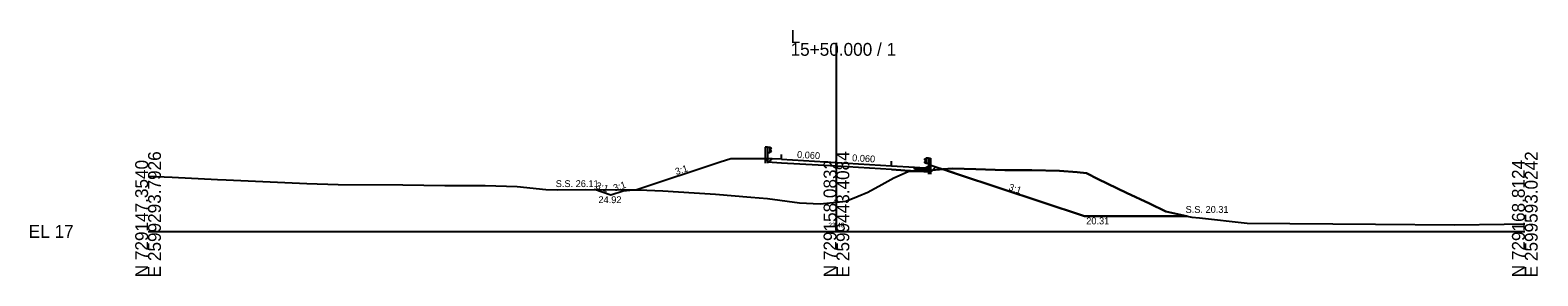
# Model space of a CAD drawing. Extents: x -26 to 3303, y -10 to 9555.
# Drawn here: x 974.3 to 1302.8, y 990.3 to 1043.9 of the extents above; entities that cross this region are included whole.
import ezdxf

# ---------------------------------------------------------------- set-up
doc = ezdxf.new("R2010")
doc.units = 0
for name, color, linetype in [('Exist Cross Section Cell', 7, 'Continuous'), ('Exist XS Center Line Elevation Label', 7, 'Continuous'), ('Exist XS Ground Line', 7, 'Continuous'), ('Prop XS Ditch Slope Text', 7, 'Continuous'), ('Prop XS Ditch Standard Text', 7, 'Continuous'), ('Prop XS Dump Level', 7, 'Continuous'), ('Prop XS Earthwork Shape', 7, 'Continuous'), ('Prop XS EOT Tick Mark', 7, 'Continuous'), ('Prop XS Finish Grade', 7, 'Continuous'), ('Prop XS Finish Grade Earthwork', 7, 'Continuous'), ('Prop XS Finish Grade Paved Shoulder', 7, 'Continuous'), ('Prop XS Finish Grade Pavement', 7, 'Continuous'), ('Prop XS Pvmt Edge Slope', 7, 'Continuous'), ('Prop XS SE Text', 7, 'Continuous'), ('Prop XS Side Slope Text', 7, 'Continuous'), ('Prop XS SS Elevation Text', 7, 'Continuous'), ('Prop XS Subgrade Earthwork', 7, 'Continuous'), ('Typical Curb CELL', 7, 'Continuous'), ('Typical Guardrail CELL', 7, 'Continuous')]:
    doc.layers.add(name, color=color, linetype=linetype)

msp = doc.modelspace()

# ---------------------------------------------------------------- linework, layer by layer
at = {"layer": 'Exist Cross Section Cell'}
for p, q in [((1150, 1000), (1150, 1041.13)), ((1000, 1000), (1150, 1000)), ((1150, 1000), (1300, 1000))]:
    msp.add_line(p, q, dxfattribs=at)
at = {"layer": 'Exist XS Ground Line'}
msp.add_lwpolyline([(1000, 1012.08), (1005.25, 1011.85), (1015.13, 1011.32), (1017, 1011.25), (1018.63, 1011.19), (1034.61, 1010.47), (1041.39, 1010.28), (1055.54, 1010.16), (1064.7, 1010.01), (1068.48, 1010.01), (1073.45, 1010), (1080.45, 1009.8), (1086.71, 1009.19), (1089.15, 1009.08), (1095.38, 1009.13), (1104.89, 1009.09), (1108.68, 1009.02), (1112.17, 1008.87), (1118.98, 1008.42), (1123.67, 1008.15), (1131.38, 1007.46), (1134.99, 1007.19), (1141.95, 1006.24), (1146.45, 1006), (1150, 1006.4), (1152.08, 1006.64), (1154.75, 1007.7), (1156.83, 1008.6), (1159.91, 1010.26), (1162.5, 1011.68), (1165.66, 1013.06), (1169.68, 1013.3), (1175.28, 1013.71), (1180.39, 1013.57), (1186.71, 1013.37), (1192.61, 1013.36), (1198.62, 1013.23), (1202.42, 1012.94), (1204.51, 1012.74), (1207.06, 1011.42), (1213.21, 1008.46), (1218.19, 1006.11), (1221.75, 1004.32), (1226.33, 1003.33), (1227.47, 1003.12), (1229.11, 1002.94), (1239.52, 1001.78), (1267.47, 1001.58), (1284.68, 1001.41), (1295.49, 1001.59), (1300, 1001.65)], dxfattribs=at)
at = {"layer": 'Prop XS Dump Level'}
for p, q in [((1138, 1015.76), (1150, 1015.04)), ((1150, 1015.04), (1162, 1014.32))]:
    msp.add_line(p, q, dxfattribs=at)
at = {"layer": 'Prop XS Earthwork Shape'}
for points in [[(1135.21, 1015.1), (1134.43, 1015.88), (1127, 1015.88), (1124.64, 1015.1), (1106.52, 1009.06), (1108.68, 1009.02), (1112.17, 1008.87), (1118.98, 1008.42), (1123.67, 1008.15), (1131.38, 1007.46), (1134.99, 1007.19), (1141.95, 1006.24), (1146.45, 1006), (1150, 1006.4), (1152.08, 1006.64), (1154.75, 1007.7), (1156.83, 1008.6), (1159.91, 1010.26), (1162.5, 1011.68), (1165.66, 1013.06), (1167.44, 1013.16), (1164.89, 1013.32), (1164, 1013.37), (1162, 1013.49), (1150, 1014.21), (1138, 1014.93), (1136, 1015.05)], [(1138, 1014.93), (1136, 1015.05), (1135.21, 1015.1), (1134.43, 1015.88), (1127, 1015.88), (1124.64, 1015.1), (1106.52, 1009.06), (1108.68, 1009.02), (1112.17, 1008.87), (1118.98, 1008.42), (1123.67, 1008.15), (1131.38, 1007.46), (1134.99, 1007.19), (1141.95, 1006.24), (1146.45, 1006), (1150, 1006.4), (1152.08, 1006.64), (1154.75, 1007.7), (1156.83, 1008.6), (1159.91, 1010.26), (1162.5, 1011.68), (1165.66, 1013.06), (1167.44, 1013.16), (1164.89, 1013.32), (1164, 1013.37), (1162, 1013.49), (1150, 1014.21)], [(1170.56, 1012.98), (1170.98, 1013.4), (1169.68, 1013.3), (1167.44, 1013.16)], [(1170.56, 1012.98), (1170.98, 1013.4), (1169.68, 1013.3), (1167.44, 1013.16)], [(1170.98, 1013.4), (1171.68, 1014.09), (1173.26, 1013.56)], [(1171.68, 1014.09), (1173.26, 1013.56), (1170.98, 1013.4)], [(1173.26, 1013.56), (1176.4, 1012.52), (1204.02, 1003.31), (1226.43, 1003.31), (1226.33, 1003.33), (1221.75, 1004.32), (1218.19, 1006.11), (1213.21, 1008.46), (1207.06, 1011.42), (1204.51, 1012.74), (1202.42, 1012.94), (1198.62, 1013.23), (1192.61, 1013.36), (1186.71, 1013.37), (1180.39, 1013.57), (1175.28, 1013.71)], [(1173.26, 1013.56), (1175.28, 1013.71), (1180.39, 1013.57), (1186.71, 1013.37), (1192.61, 1013.36), (1198.62, 1013.23), (1202.42, 1012.94), (1204.51, 1012.74), (1207.06, 1011.42), (1213.21, 1008.46), (1218.19, 1006.11), (1221.75, 1004.32), (1226.33, 1003.33), (1226.43, 1003.31), (1204.02, 1003.31), (1176.4, 1012.52)], [(1106.52, 1009.06), (1103.52, 1008.81), (1100.86, 1007.92), (1097.25, 1009.12), (1104.89, 1009.09)], [(1106.52, 1009.06), (1103.52, 1008.81), (1100.86, 1007.92), (1097.25, 1009.12), (1104.89, 1009.09)]]:
    msp.add_lwpolyline(points, close=True, dxfattribs=at)
at = {"layer": 'Prop XS EOT Tick Mark'}
for p, q in [((1138, 1015.76), (1138, 1016.76)), ((1162, 1014.32), (1162, 1015.32))]:
    msp.add_line(p, q, dxfattribs=at)
at = {"layer": 'Prop XS Finish Grade'}
for p, q in [((1136, 1015.88), (1134.43, 1015.88)), ((1170.03, 1014.21), (1170.56, 1014.46)), ((1170.56, 1014.46), (1171.68, 1014.09))]:
    msp.add_line(p, q, dxfattribs=at)
at = {"layer": 'Prop XS Finish Grade Earthwork'}
for p, q in [((1127, 1015.88), (1124.64, 1015.1)), ((1134.43, 1015.88), (1127, 1015.88)), ((1124.64, 1015.1), (1106.52, 1009.06)), ((1171.68, 1014.09), (1176.4, 1012.52)), ((1176.4, 1012.52), (1204.02, 1003.31)), ((1100.86, 1007.92), (1097.25, 1009.12)), ((1103.52, 1008.81), (1100.86, 1007.92)), ((1106.52, 1009.06), (1103.52, 1008.81)), ((1226.43, 1003.31), (1204.02, 1003.31))]:
    msp.add_line(p, q, dxfattribs=at)
at = {"layer": 'Prop XS Finish Grade Paved Shoulder'}
for p, q in [((1138, 1015.76), (1136, 1015.88)), ((1162, 1014.32), (1167, 1014.02))]:
    msp.add_line(p, q, dxfattribs=at)
at = {"layer": 'Prop XS Finish Grade Pavement'}
for p, q in [((1138, 1015.76), (1150, 1015.04)), ((1150, 1015.04), (1162, 1014.32))]:
    msp.add_line(p, q, dxfattribs=at)
at = {"layer": 'Prop XS Pvmt Edge Slope'}
for p, q in [((1135.21, 1015.1), (1134.43, 1015.88)), ((1136, 1015.88), (1135.21, 1015.1)), ((1170.01, 1013.53), (1170.56, 1012.98)), ((1170.56, 1012.98), (1171.68, 1014.09))]:
    msp.add_line(p, q, dxfattribs=at)
at = {"layer": 'Prop XS Subgrade Earthwork'}
for p, q in [((1135.21, 1015.1), (1134.43, 1015.88)), ((1136, 1015.05), (1135.21, 1015.1)), ((1138, 1014.93), (1136, 1015.05)), ((1150, 1014.21), (1138, 1014.93)), ((1162, 1013.49), (1150, 1014.21)), ((1162, 1013.49), (1164, 1013.37)), ((1164, 1013.37), (1164.89, 1013.32)), ((1164.89, 1013.32), (1170.56, 1012.98)), ((1170.56, 1012.98), (1171.68, 1014.09))]:
    msp.add_line(p, q, dxfattribs=at)
at = {"layer": 'Typical Curb CELL'}
for p, q in [((1166.99, 1013.61), (1167, 1014.01)), ((1170.01, 1013.53), (1166.99, 1013.61)), ((1167, 1014.02), (1167, 1014.02)), ((1167.01, 1014.02), (1169.33, 1013.88)), ((1167.23, 1013.75), (1167.32, 1013.87)), ((1167.35, 1013.76), (1167.23, 1013.75)), ((1167.32, 1013.87), (1167.35, 1013.76)), ((1167.99, 1013.68), (1168.06, 1013.8)), ((1168.16, 1013.72), (1167.99, 1013.68)), ((1168.06, 1013.8), (1168.16, 1013.72)), ((1168.48, 1013.72), (1168.57, 1013.84)), ((1168.6, 1013.72), (1168.48, 1013.72)), ((1168.57, 1013.84), (1168.6, 1013.72)), ((1169.24, 1013.65), (1169.31, 1013.76)), ((1169.41, 1013.69), (1169.24, 1013.65)), ((1169.31, 1013.76), (1169.41, 1013.69)), ((1169.33, 1013.88), (1170.03, 1014.21)), ((1169.83, 1013.88), (1169.84, 1013.79)), ((1169.98, 1013.83), (1169.83, 1013.88)), ((1169.84, 1013.79), (1169.98, 1013.83)), ((1170.01, 1013.53), (1170.03, 1014.21))]:
    msp.add_line(p, q, dxfattribs=at)
for centre in [(1167.09, 1013.84), (1167.13, 1013.97), (1167.49, 1013.88), (1167.55, 1013.7), (1167.6, 1013.67), (1167.64, 1013.79), (1167.71, 1013.79), (1167.76, 1013.82), (1167.81, 1013.7), (1168, 1013.74), (1168.21, 1013.72), (1168.23, 1013.77), (1168.24, 1013.82), (1168.29, 1013.68), (1168.39, 1013.72), (1168.48, 1013.73), (1168.6, 1013.68), (1168.8, 1013.67), (1168.85, 1013.64), (1168.89, 1013.76), (1169.01, 1013.79), (1169.06, 1013.67), (1169.25, 1013.71), (1169.28, 1013.6), (1169.46, 1013.68), (1169.48, 1013.73), (1169.73, 1013.7), (1169.85, 1013.65), (1169.95, 1013.92)]:
    msp.add_circle(centre, 0.00802, dxfattribs=at)
msp.add_arc((1167.01, 1014.01), 0.0104, 86.5213, 178.5693, dxfattribs=at)
at = {"layer": 'Typical Guardrail CELL'}
for p, q in [((1135, 1018.37), (1134.5, 1018.37)), ((1134.5, 1018.37), (1134.5, 1015.88)), ((1135, 1015.88), (1134.5, 1015.88)), ((1134.5, 1015.88), (1134.5, 1014.87)), ((1135, 1018.37), (1135, 1015.88)), ((1135, 1018.37), (1135.5, 1018.37)), ((1135, 1017.21), (1135.5, 1017.21)), ((1135, 1015.88), (1135, 1014.87)), ((1135.5, 1018.37), (1135.5, 1017.21)), ((1135.5, 1018.37), (1135.79, 1018.17)), ((1135.5, 1017.84), (1135.79, 1018.04)), ((1135.5, 1017.79), (1135.5, 1017.84)), ((1135.5, 1017.79), (1135.5, 1017.74)), ((1135.5, 1017.74), (1135.79, 1017.54)), ((1135.5, 1017.21), (1135.79, 1017.41)), ((1169.53, 1015.99), (1169.24, 1015.79)), ((1169.53, 1015.46), (1169.24, 1015.66)), ((1169.53, 1015.36), (1169.24, 1015.16)), ((1170.03, 1015.99), (1169.53, 1015.99)), ((1169.53, 1015.99), (1169.53, 1014.83)), ((1169.53, 1015.41), (1169.53, 1015.46)), ((1169.53, 1015.41), (1169.53, 1015.36)), ((1170.03, 1015.99), (1170.03, 1013.5)), ((1170.03, 1015.99), (1170.53, 1015.99)), ((1170.53, 1015.99), (1170.53, 1013.5)), ((1169.53, 1014.83), (1169.24, 1015.03)), ((1170.03, 1014.83), (1169.53, 1014.83)), ((1170.03, 1013.5), (1170.53, 1013.5)), ((1170.03, 1013.5), (1170.03, 1012.5)), ((1170.53, 1013.5), (1170.53, 1012.5))]:
    msp.add_line(p, q, dxfattribs=at)
for centre, start, end in [((1135.74, 1018.1), 304.9888, 54.997), ((1135.74, 1017.48), 304.9634, 54.9941), ((1169.29, 1015.72), 125.003, 235.0112), ((1169.29, 1015.1), 125.0059, 235.0366)]:
    msp.add_arc(centre, 0.0776, start, end, dxfattribs=at)

# ---------------------------------------------------------------- texts
at = {"layer": 'Exist Cross Section Cell'}
for s, p in [('L', (1140, 1041.13)), ('15+50.000 / 1', (1140, 1038.33)), ('EL 17', (974, 998.6))]:
    msp.add_text(s, height=2.8, dxfattribs=at).set_placement(p)
for s, p in [('N 729147.3540', (1000, 990)), ('E 2599293.7926', (1002.8, 990)), ('N 729158.0832', (1150, 990)), ('E 2599443.4084', (1152.8, 990)), ('N 729168.8124', (1300, 990)), ('E 2599593.0242', (1302.8, 990))]:
    msp.add_text(s, height=2.8, rotation=90, dxfattribs=at).set_placement(p)
at = {"layer": 'Exist XS Center Line Elevation Label'}
msp.add_text('23.40', height=1, dxfattribs=at).set_placement((1148.25, 1000.9))
at = {"layer": 'Prop XS Ditch Slope Text'}
msp.add_text('3:1', height=1.5, rotation=340.5558, dxfattribs=at).set_placement((1187.38, 1009.1))
at = {"layer": 'Prop XS Ditch Standard Text'}
msp.add_text('20.31', height=1.5, dxfattribs=at).set_placement((1204.43, 1001.56))
at = {"layer": 'Prop XS Dump Level'}
for p in [(1130, 1015.84), (1170, 1013.68), (1173, 1013.44)]:
    msp.add_text('Case1', height=0.04, dxfattribs=at).set_placement(p)
at = {"layer": 'Prop XS SE Text'}
for p in [(1141.38, 1016.06), (1153.38, 1015.34)]:
    msp.add_text('0.060', height=1.5, rotation=356.5664, dxfattribs=at).set_placement(p)
at = {"layer": 'Prop XS Side Slope Text'}
for rotation, p in [(18.4349, (1115.13, 1012.28)), (341.0185, (1097.41, 1009.42)), (18.4349, (1101.65, 1008.7))]:
    msp.add_text('3:1', height=1.5, rotation=rotation, dxfattribs=at).set_placement(p)
at = {"layer": 'Prop XS SS Elevation Text'}
for s, p in [('S.S. 26.11', (1088.83, 1009.68)), ('24.92', (1098.14, 1006.18)), ('S.S. 20.31', (1226.08, 1004.05))]:
    msp.add_text(s, height=1.5, dxfattribs=at).set_placement(p)

doc.saveas('drawing.dxf')
